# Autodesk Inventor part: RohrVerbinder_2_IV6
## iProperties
Shininess: 64.0
Length Units: 11269
Angle Units: 11279
Time Units: 11290
Mass Units: 11283
Length Display Precision: 5
Angle Display Precision: 5
Compacted: True
Part Number: RohrVerbinder_2_IV6
Document SubType Name: Modeling
Created: 2005-04
Material: Aluminium - 6061
Designer: mp
Density: 0.0
Volumn: 0.0
Area: 0.0
PropertySet Name: Model Information
Control State: 0
Master: False
Checked Out: False
Author: mp
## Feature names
1. Extrusion1
2. Extrusion2
3. Erhebung1
4. Bohrung1 [Hole]
5. Spiegeln1 [Mirror]
6. Rundung1 [Fillet]
7. Fase1 [Chamfer]
